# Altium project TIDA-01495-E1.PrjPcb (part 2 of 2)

## Sheet TIDA-01495-LLC.SchDoc: LLC
size 431 x 317 mm; Date: Not shown in title block; ApprovedBy: Not shown in title block; CheckedBy: Not shown in title block; Author: Not shown in title block; CompanyName: Not shown in title block; DrawnBy: Ramkumar S; Engineer: Ramkumar S; Organization: Not shown in title block; Address1: Not shown in title block; Address2: Not shown in title block; Address3: Not shown in title block; Address4: Not shown in title block; DocumentNumber: 1; Revision: Use project parameter SCH_Rev; SheetNumber: 3; SheetTotal: 4; PageSetup: Record=PageOptions¦CenterHorizontal=True¦CenterVertical=True¦PrintScale=1.00¦XCorrection=1.00¦YCorrection=1.00¦PrintKind=0¦BorderSize=5000000¦LeftOffset=0¦BottomOffset=0¦Orientation=2¦PaperLength=1000¦PaperWidth=1000¦Scale=100¦PaperSource=15¦PrintQuality=600¦MediaType=1¦DitherType=10¦PaperKind=Letter¦PrintScaleMode=1
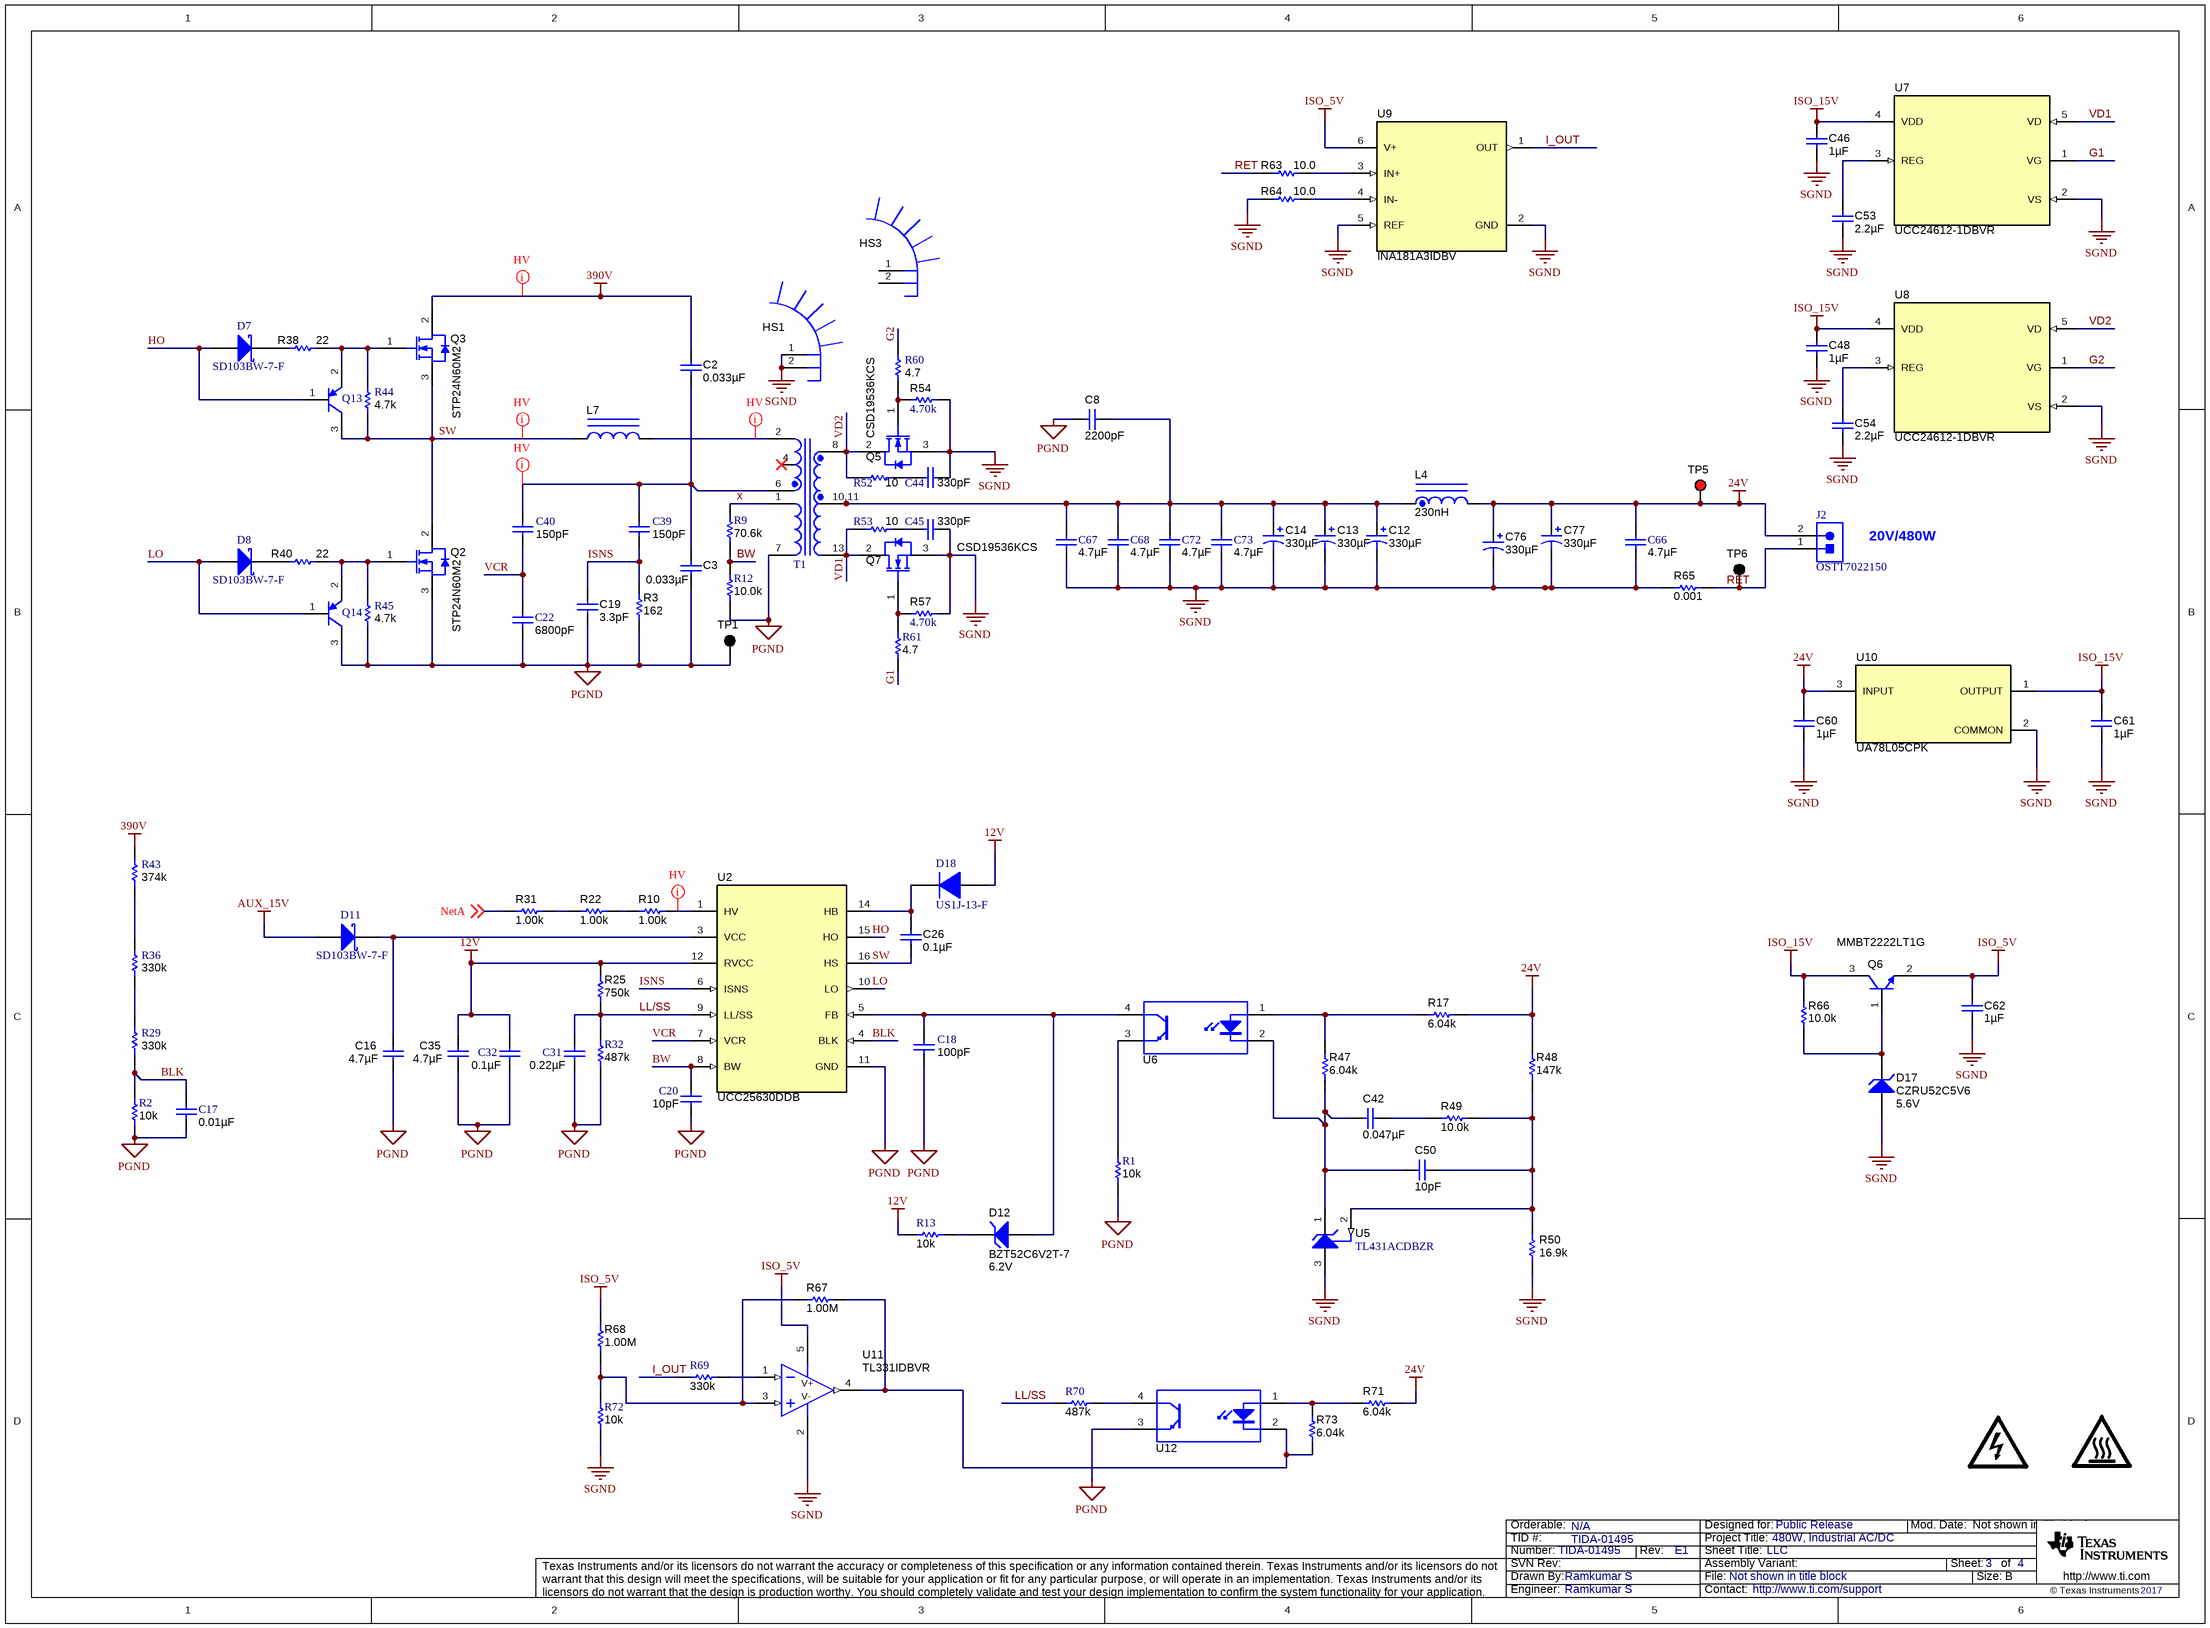
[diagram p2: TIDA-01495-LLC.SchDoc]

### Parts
(Parts that share a designator on the sheet are numbered #1, #2 ... from top to bottom, then left to right.)
C2  ValueDisplayed: 0.033µF  [B32652_1800x700x1250]  (hidden comment: B32642B0333J)
C3  ValueDisplayed: 0.033µF  [B32652_1800x700x1250]  (hidden comment: B32642B0333J)
C8  ValueDisplayed: 2200pF  [CD45_700x600x1100]  (hidden comment: AY2222M35Y5US63L7)
C12  ValueDisplayed: 330µF  [Chemi-Con_1000x2000]  (hidden comment: 35ZLH330MEFC10X12.5)
C13  ValueDisplayed: 330µF  [Chemi-Con_1000x2000]  (hidden comment: 35ZLH330MEFC10X12.5)
C14  ValueDisplayed: 330µF  [Chemi-Con_1000x2000]  (hidden comment: 35ZLH330MEFC10X12.5)
C16  ValueDisplayed: 4.7µF  [0603]  (hidden comment: 0603ZD475KAT2A)
C17  ValueDisplayed: 0.01µF  [0603]  (hidden comment: 06031C103JAT2A)
C18  ValueDisplayed: 100pF  [0603]  (hidden comment: C0603C101J5GAC)
C19  ValueDisplayed: 3.3pF  [0805_HV1]  (hidden comment: 08055A3R3CAT2A)
C20  ValueDisplayed: 10pF  [0603]  (hidden comment: 06035A100JAT2A)
C22  ValueDisplayed: 6800pF  [0603]  (hidden comment: GRM188R71H682KA01D)
C26  ValueDisplayed: 0.1µF  [0805_HV1]  (hidden comment: C0805C104K1RACTU)
C31  ValueDisplayed: 0.22µF  [0603]  (hidden comment: 06033D224KAT2A)
C32  ValueDisplayed: 0.1µF  [0603]  (hidden comment: GRM188R72A104KA35J)
C35  ValueDisplayed: 4.7µF  [0603]  (hidden comment: 0603ZD475KAT2A)
C39  ValueDisplayed: 150pF  [1206]  (hidden comment: GRM31A7U3A151JW31D)
C40  ValueDisplayed: 150pF  [1206]  (hidden comment: GRM31A7U3A151JW31D)
C42  ValueDisplayed: 0.047µF  [0603]  (hidden comment: GRM188R71C473KA01D)
C44  ValueDisplayed: 330pF  [0603]  (hidden comment: GRM1885C2A331JA01D)
C45  ValueDisplayed: 330pF  [0603]  (hidden comment: GRM1885C2A331JA01D)
C46  ValueDisplayed: 1µF  [0805_HV1]  (hidden comment: C0805C105K3RACTU)
C48  ValueDisplayed: 1µF  [0805_HV1]  (hidden comment: C0805C105K3RACTU)
C50  ValueDisplayed: 10pF  [0603]  (hidden comment: 06035A100JAT2A)
C53  ValueDisplayed: 2.2µF  [0603]  (hidden comment: C1608X6S1C225K080AC)
C54  ValueDisplayed: 2.2µF  [0603]  (hidden comment: C1608X6S1C225K080AC)
C60  ValueDisplayed: 1µF  [0603]  (hidden comment: GRM188R71E105KA12D)
C61  ValueDisplayed: 1µF  [0603]  (hidden comment: GRM188R71E105KA12D)
C62  ValueDisplayed: 1µF  [0603]  (hidden comment: GRM188R71E105KA12D)
C66  ValueDisplayed: 4.7µF  [1210]  (hidden comment: C3225X7S2A475K200AE)
C67  ValueDisplayed: 4.7µF  [1210]  (hidden comment: C3225X7S2A475K200AE)
C68  ValueDisplayed: 4.7µF  [1210]  (hidden comment: C3225X7S2A475K200AE)
C72  ValueDisplayed: 4.7µF  [1210]  (hidden comment: C3225X7S2A475K200AE)
C73  ValueDisplayed: 4.7µF  [1210]  (hidden comment: C3225X7S2A475K200AE)
C76  ValueDisplayed: 330µF  [Chemi-Con_1000x2000]  (hidden comment: 35ZLH330MEFC10X12.5)
C77  ValueDisplayed: 330µF  [Chemi-Con_1000x2000]  (hidden comment: 35ZLH330MEFC10X12.5)
D7  SD103BW-7-F  [SOD-123]
D8  SD103BW-7-F  [SOD-123]
D11  SD103BW-7-F  [SOD-123]
D12  BZT52C6V2T-7  value 6.2V  [SOD-523]
D17  CZRU52C5V6  value 5.6V  [SOD-523F]
D18  US1J-13-F  [SMA]
HS1  782653B04250G  [HEATSINK_782653B04250G]  (value not drawn)
HS3  782653B04250G  [HEATSINK_782653B04250G]  (value not drawn)
J2  OSTT7022150  [TERM_BLK_OSTT7022150]
L4  ValueDisplayed: 230nH  [THCBR1290]  (hidden comment: THCBR1290-231IN)
L7  (no value)  [IND_CUST]
LOGO?#5  DANGER HIGH VOLTAGE  [IEC_HighVoltage_Small]  (value not drawn)  (graphical)
LOGO?#6  CAUTION HOT SURFACE  [IEC_HotSurface_Small]  (value not drawn)  (graphical)
Q2  STP24N60M2  [TO-220AB_HORIZONTAL]
Q3  STP24N60M2  [TO-220AB_HORIZONTAL]
Q5  CSD19536KCS  [TO-220AB_HORIZONTAL]
Q6  MMBT2222LT1G  [SOT-23]
Q7  CSD19536KCS  [TO-220AB_HORIZONTAL]
Q13  BC858C-7-F  [SOT-23]  (value not drawn)
Q14  BC858C-7-F  [SOT-23]  (value not drawn)
R1  ValueDisplayed: 10k  [0603]  (hidden comment: RNCF0603TKY10K0)
R2  ValueDisplayed: 10k  [0603]  (hidden comment: RNCF0603TKY10K0)
R3  ValueDisplayed: 162  [0805_HV1]  (hidden comment: CRCW0805162RFKEA)
R9  ValueDisplayed: 70.6k  [0603]  (hidden comment: RT0603DRE0770K6L)
R10  ValueDisplayed: 1.00k  [1206]  (hidden comment: CRCW12061K00FKEA)
R12  ValueDisplayed: 10.0k  [0603]  (hidden comment: CRCW060310K0FKEA)
R13  ValueDisplayed: 10k  [0603]  (hidden comment: RNCF0603TKY10K0)
R17  ValueDisplayed: 6.04k  [0603]  (hidden comment: CRCW06036K04FKEA)
R22  ValueDisplayed: 1.00k  [1206]  (hidden comment: CRCW12061K00FKEA)
R25  ValueDisplayed: 750k  [0603]  (hidden comment: CRCW0603750KFKEA)
R29  ValueDisplayed: 330k  [1206]  (hidden comment: CRCW1206330KJNEA)
R31  ValueDisplayed: 1.00k  [1206]  (hidden comment: CRCW12061K00FKEA)
R32  ValueDisplayed: 487k  [0603]  (hidden comment: CRCW0603487KFKEA)
R36  ValueDisplayed: 330k  [1206]  (hidden comment: CRCW1206330KJNEA)
R38  ValueDisplayed: 22  [0603]  (hidden comment: CRCW060322R0JNEA)
R40  ValueDisplayed: 22  [0603]  (hidden comment: CRCW060322R0JNEA)
R43  ValueDisplayed: 374k  [1206]  (hidden comment: CRCW1206374KFKEA)
R44  ValueDisplayed: 4.7k  [0603]  (hidden comment: CR0603-JW-472GLF)
R45  ValueDisplayed: 4.7k  [0603]  (hidden comment: CR0603-JW-472GLF)
R47  ValueDisplayed: 6.04k  [0603]  (hidden comment: CRCW06036K04FKEA)
R48  ValueDisplayed: 147k  [0603]  (hidden comment: CRCW0603147KFKEA)
R49  ValueDisplayed: 10.0k  [0603]  (hidden comment: CRCW060310K0FKEA)
R50  ValueDisplayed: 16.9k  [0603]  (hidden comment: CRCW060316K9FKEA)
R52  ValueDisplayed: 10  [0805_HV1]  (hidden comment: CRCW080510R0JNEA)
R53  ValueDisplayed: 10  [0805_HV1]  (hidden comment: CRCW080510R0JNEA)
R54  ValueDisplayed: 4.70k  [1206]  (hidden comment: RC1206FR-074K7L)
R57  ValueDisplayed: 4.70k  [1206]  (hidden comment: RC1206FR-074K7L)
R60  ValueDisplayed: 4.7  [0805_HV1]  (hidden comment: CRCW08054R70JNEA)
R61  ValueDisplayed: 4.7  [0805_HV1]  (hidden comment: CRCW08054R70JNEA)
R63  ValueDisplayed: 10.0  [0603]  (hidden comment: RC0603FR-0710RL)
R64  ValueDisplayed: 10.0  [0603]  (hidden comment: RC0603FR-0710RL)
R65  ValueDisplayed: 0.001  [2512]  (hidden comment: ERJ-M1WTF1M0U)
R66  ValueDisplayed: 10.0k  [0603]  (hidden comment: CRCW060310K0FKEA)
R67  ValueDisplayed: 1.00M  [0603]  (hidden comment: MCT06030C1004FP500)
R68  ValueDisplayed: 1.00M  [0603]  (hidden comment: MCT06030C1004FP500)
R69  ValueDisplayed: 330k  [1206]  (hidden comment: CRCW1206330KJNEA)
R70  ValueDisplayed: 487k  [0603]  (hidden comment: CRCW0603487KFKEA)
R71  ValueDisplayed: 6.04k  [0603]  (hidden comment: CRCW06036K04FKEA)
R72  ValueDisplayed: 10k  [0603]  (hidden comment: RNCF0603TKY10K0)
R73  ValueDisplayed: 6.04k  [0603]  (hidden comment: CRCW06036K04FKEA)
T1  58599  [WE_750343661_CUS]  (value not drawn)
TP1  5001  [Keystone5001]  (value not drawn)
TP5  5000  [Keystone5000]  (value not drawn)
TP6  5001  [Keystone5001]  (value not drawn)
U2  UCC25630DDB  [DDB0014A]
U5  TL431ACDBZR  [DBZ0003A_N]
U6  VO618A  [DIP-4]  (value not drawn)
U7  UCC24612-1DBVR  [DBV0005A_N]
U8  UCC24612-1DBVR  [DBV0005A_N]
U9  INA181A3IDBV  [DBV0006A_N]
U10  UA78L05CPK  [PK0003A_M]
U11  TL331IDBVR  [DBV0005A_N]
U12  VO618A  [DIP-4]  (value not drawn)

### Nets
12V: C32.1 C35.1 D18.2(A) R13.1 R25.2 U2.12(RVCC)
24V: C60.1 C66.1 C76.1(+) C77.1(+) J2.2 L4.2 R17.2 R48.2 R71.2 TP5.1 U10.3(INPUT)
390V: C2.1 Q3.2(D) R43.2
AUX_15V: D11.2(A)
ISO_5V: C62.1 Q6.2(E) R68.2 U9.6(V+) U11.5(V+)
ISO_15V: C46.1 C48.1 C61.1 Q6.3(C) R66.1 U7.4(VDD) U8.4(VDD) U10.1(OUTPUT)
PGND: C3.2 C8.2 C16.2 C17.1 C18.2 C19.2 C20.2 C22.2 C31.2 C32.2 C35.2 Q2.3(S) Q14.3(C) R1.1 R2.1 R3.1 R12.1 R32.1 R45.1 T1.7 TP1.1 U2.11(GND) U12.3(E)
SGND: C12.2(-) C13.2(-) C14.2(-) C44.1 C45.1 C46.2 C48.2 C53.2 C54.2 C60.2 C61.2 C62.2 C66.2 C67.2 C68.2 C72.2 C73.2 C76.2(-) C77.2(-) D17.2(A) HS1.1 HS1.2 Q5.3(S) Q7.3(S) R50.1 R54.2 R57.2 R64.1 R65.1 R72.1 U5.3(ANODE) U7.2(VS) U8.2(VS) U9.2(GND) U9.5(REF) U10.2(COMMON) U11.2(V-/GND)
BLK: C17.2 R2.2 R29.1 U2.4(BLK)
BW: C20.1 R9.1 R12.2 U2.8(BW)
G1: R61.1 U7.1(VG)
G2: R60.2 U8.1(VG)
HO: D7.2(A) Q13.1(B) U2.15(HO)
I_OUT: R69.2 U9.1(OUT)
ISNS: C19.1 C39.2 R3.2 U2.6(ISNS)
LL/SS: C31.1 R25.1 R32.2 R70.2 U2.9(LL/SS)
LO: D8.2(A) Q14.1(B) U2.10(LO)
NetA: R31.1 ; off-sheet NetA
RET: J2.1 R63.1 R65.2 TP6.1
SW: C26.2 L7.1 Q2.2(D) Q3.3(S) Q13.3(C) R44.1 U2.16(HS)
VCR: C22.1 C40.2 U2.7(VCR)
VD1: Q7.2(D) R53.1 T1.13 U7.5(VD)
VD2: Q5.2(D) R52.1 T1.8 U8.5(VD)
x: R9.2 T1.1
NetC2_2: C2.2 C3.1 C39.1 C40.1 T1.6
NetC8_1: C8.1 C12.1(+) C13.1(+) C14.1(+) C67.1 C68.1 C72.1 C73.1 L4.1 T1.10,11 T1.11
NetC16_1: C16.1 D11.1(K) U2.3(VCC)
NetC18_1: C18.1 D12.2(A) U2.5(FB) U6.4(C)
NetC26_1: C26.1 D18.1(K) U2.14(HB)
NetC42_1: C42.1 R49.1
NetC42_2: C42.2 C50.2 R47.1 U5.1(CATHODE) U6.2(K)
NetC44_2: C44.2 R52.2
NetC45_2: C45.2 R53.2
NetC50_1: C50.1 R48.1 R49.2 R50.2 U5.2(REF)
NetC53_1: C53.1 U7.3(REG)
NetC54_1: C54.1 U8.3(REG)
NetD7_1: D7.1(K) R38.1
NetD8_1: D8.1(K) R40.1
NetD12_1: D12.1(K) R13.2
NetD17_1: D17.1(K) Q6.1(B) R66.2
NetL7_2: L7.2 T1.2
NetQ2_1: Q2.1(G) Q14.2(E) R40.2 R45.2
NetQ3_1: Q3.1(G) Q13.2(E) R38.2 R44.2
NetQ5_1: Q5.1(G) R54.1 R60.1
NetQ7_1: Q7.1(G) R57.1 R61.2
NetR1_2: R1.2 U6.3(E)
NetR10_1: R10.1 R22.2
NetR10_2: R10.2 U2.1(HV)
NetR17_1: R17.1 R47.2 U6.1(A)
NetR22_1: R22.1 R31.2
NetR29_2: R29.2 R36.1
NetR36_2: R36.2 R43.1
NetR63_2: R63.2 U9.3(IN+)
NetR64_2: R64.2 U9.4(IN-)
NetR67_1: R67.1 R68.1 R72.2 U11.3(IN+)
NetR67_2: R67.2 R73.1 U11.4(OUT) U12.2(K)
NetR69_1: R69.1 U11.1(IN-)
NetR70_1: R70.1 U12.4(C)
NetR71_1: R71.1 R73.2 U12.1(A)

Not connected (* = marked no-connect by the designer): HS3 1 2; T1 4*

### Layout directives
net class HV: 390V, NetC2_2, NetL7_2, NetR10_2, SW

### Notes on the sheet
- 20V/480W

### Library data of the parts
C2 C3 = B32652A7153J000: CAP FILM 0.033UF 5% 1KVDC RADIAL; Manufacturer: TDK; Polarized: N; CompType: Capacitor; U/M: EA; Cap_F: 0.000000033; Tolerance_%: 5; VDC_V: 1250; Value2: 1250V; TaMin_C: -55; TaMax_C: 100; Cap_Case: 18x7x12.5; SizeAreaWB_mm2: 180; SizeArea_mm2: 126; SizeX_mm: 18; SizeY_mm: 7; SizeZ_mm: 12.5; AEC Category: Q200; AEC Qualified: Y; AEC Grade: 3; Green_Lifecycle: Not Set; Green_REACh: Incomplete; VAC: 500
C8 = AY2222M35Y5US63L7: CAP, CERM, 2200 pF, 300 V, +/- 20%, Y5U, AEC-Q200 Grade 1, D9.5xT5mm; Manufacturer: Vishay-Bccomponents; Polarized: N; CompType: Capacitor; Value: 2200pF; U/M: EA; Cap_F: 0.0000000022; Tolerance_%: 20; Value1: Unknown; VDC_V: 300; Value2: 300V; TaMin_C: -55; TaMax_C: 125; Cap_Case: 9.5x5mm; SizeArea_mm2: 47.5; SizeAreaWB_mm2: 80.5; SizeX_mm: 9.5; SizeY_mm: 5; SizeZ_mm: 14.5; AEC Category: Q200; AEC Qualified: Y; AEC Grade: 1
C12-C14 C76 C77 = EKZE350ELL471MJ20S: CAP, AL, 330 µF, 35 V, +/- 20%, TH; Manufacturer: Rubycon; Polarized: Y; CompType: Capacitor; Value: 330uF; U/M: EA; Cap_F: 0.00047; Tolerance_%: 20; VDC_V: 35; Value2: 35V; IRMS_A: 1.82; TaMin_C: -40; TaMax_C: 105; Cap_Case: 10x20; SizeAreaWB_mm2: 144; SizeArea_mm2: 100; SizeX_mm: 10; SizeZ_mm: 21.5; AEC Category: Q200; AEC Qualified: N
C16 C35 = 0603ZD475KAT2A: CAP, CERM, 4.7 µF, 10 V, +/- 10%, X5R, 0603; Manufacturer: AVX; Polarized: N; CompType: Capacitor; Value: 4.7uF; U/M: EA; Cap_F: 0.0000047; Tolerance_%: 10; Value1: Unknown; Value2: 10V; TaMin_C: -55; TaMax_C: 85; SizeArea_mm2: 1.28; SizeAreaWB_mm2: 4.68; SizeX_mm: 1.6; SizeY_mm: 0.8; SizeZ_mm: 1; AEC Category: Q200; Green_Lifecycle: Active; Green_REACh: Passed
C17 = 06031C103JAT2A: CAP, CERM, 0.01 µF, 100 V, +/- 5%, X7R, 0603; Manufacturer: AVX; Polarized: N; CompType: Capacitor; Value: 0.01uF; U/M: EA; Cap_F: 0.00000001; Tolerance_%: 5; ESR_ohm: 0.098; Value1: 0.098 ohm; VDC_V: 100; Value2: 100V; TaMin_C: -55; TaMax_C: 125
C18 = C0603C101J5GAC: CAP, CERM, 100 pF, 50 V, +/- 5%, C0G/NP0, 0603; Manufacturer: Kemet; Polarized: N; CompType: Capacitor; Value: 100pF; U/M: EA; Cap_F: 0.0000000001; Tolerance_%: 5; Value1: Unknown; VDC_V: 50; Value2: 50V; TaMin_C: -55; TaMax_C: 125
C19 = 08055A3R3CAT2A: CAP, CERM, 3.3 pF, 50 V, +/- 8%, C0G/NP0, 0805; Manufacturer: AVX; Polarized: N; CompType: Capacitor; Value: 3.3pF; U/M: EA; Cap_F: 0.0000000000033; Tolerance_%: 8; ESR_ohm: 3.467; Value1: 3.467 ohm; VDC_V: 50; Value2: 50V; TaMin_C: -55; TaMax_C: 125; Cap_Case: 0805; SizeArea_mm2: 2.5; SizeAreaWB_mm2: 6.75; SizeX_mm: 2; SizeY_mm: 1.25; SizeZ_mm: 1.45; AEC Category: Q200; Green_Lifecycle: Not Set; Green_REACh: Incomplete
C20 = 06035A100JAT2A: CAP, CERM, 10 pF, 50 V, +/- 5%, C0G/NP0, 0603; Manufacturer: AVX; Polarized: N; CompType: Capacitor; Value: 10pF; U/M: EA; Cap_F: 0.00000000001; Tolerance_%: 5; ESR_ohm: 0.403; Value1: 0.403 ohm; VDC_V: 50; Value2: 50V; TaMin_C: -55; TaMax_C: 125
C22 = GRM188R71H682KA01D: CAP, CERM, 6800 pF, 50 V, +/- 10%, X7R, 0603; Manufacturer: MuRata; Polarized: N; CompType: Capacitor; Value: 6800pF; U/M: EA; Cap_F: 0.0000000068; Tolerance_%: 10; Value1: Unknown; VDC_V: 50; Value2: 50V; TaMin_C: -55; TaMax_C: 125
C26 = C0805C104K1RACTU: CAP, CERM, 0.1 µF, 100 V,+/- 10%, X7R, 0805; Manufacturer: Kemet; Polarized: N; CompType: Capacitor; Value: 0.1uF; U/M: EA; Cap_F: 0.0000001; Tolerance_%: 10; ESR_ohm: 0.064; Value1: 0.064 ohm; VDC_V: 100; Value2: 100V; IRMS_A: 1.64; TaMin_C: -55; TaMax_C: 125; Cap_Case: 0805; SizeArea_mm2: 2.5; SizeAreaWB_mm2: 6.75; SizeX_mm: 2; SizeY_mm: 1.25; SizeZ_mm: 1.45; AEC Category: Q200; Green_Lifecycle: Active; Green_REACh: Passed
C31 = 06033D224KAT2A: CAP, CERM, 0.22 µF, 25 V, +/- 10%, X5R, 0603; Manufacturer: AVX; Polarized: N; CompType: Capacitor; Value: 0.22uF; U/M: EA; Cap_F: 0.00000022; Tolerance_%: 10; ESR_ohm: 0.036; Value1: 0.036 ohm; VDC_V: 25; Value2: 25V; TaMin_C: -55; TaMax_C: 85
C32 = GRM188R72A104KA35J: CAP, CERM, 0.1 µF, 100 V, +/- 10%, X7R, 0603; Manufacturer: MuRata; Polarized: N; CompType: Capacitor; Value: 0.1uF; U/M: EA; Cap_F: 0.0000001; Tolerance_%: 10; Value1: Unknown; VDC_V: 100; Value2: 100V; TaMin_C: -55; TaMax_C: 125
C39 C40 = GRM31A7U3A151JW31D: CAP, CERM, 150 pF, 1000 V, +/- 5%, U2J, 1206; Manufacturer: MuRata; Polarized: N; CompType: Capacitor; Value: 150pF; U/M: EA; Cap_F: 0.00000000015; Tolerance_%: 5; Value1: Unknown; VDC_V: 1000; Value2: 1000V; TaMin_C: -55; TaMax_C: 125
C42 = GRM188R71C473KA01D: CAP, CERM, 0.047 µF, 16 V,+/- 10%, X7R, 0603; Manufacturer: MuRata; Polarized: N; CompType: Capacitor; Value: 0.047uF; U/M: EA; Cap_F: 0.000000047; Tolerance_%: 10; VDC_V: 16; Value2: 16V; TaMin_C: -55; TaMax_C: 125; SizeArea_mm2: 1.28; SizeAreaWB_mm2: 4.68; SizeX_mm: 1.6; SizeY_mm: 0.8; SizeZ_mm: 1; AEC Category: Q200; Green_Lifecycle: Active; Green_REACh: Passed
C44 C45 = GRM1885C2A331JA01D: CAP, CERM, 330 pF, 100 V, +/- 5%, C0G/NP0, 0603; Manufacturer: MuRata; Polarized: N; CompType: Capacitor; Value: 330pF; U/M: EA; Cap_F: 0.00000000033; Tolerance_%: 5; Value1: Unknown; VDC_V: 100; Value2: 100V; TaMin_C: -55; TaMax_C: 125
C46 C48 = C0805C105K3RACTU: CAP, CERM, 1 µF, 25 V, +/- 10%, X7R, 0805; Manufacturer: Kemet; Polarized: N; CompType: Capacitor; Value: 1uF; U/M: EA; Cap_F: 0.000001; Tolerance_%: 10; Value1: Unknown; VDC_V: 25; Value2: 25V; TaMin_C: -55; TaMax_C: 125; Cap_Case: 0805; SizeArea_mm2: 2.5; SizeAreaWB_mm2: 6.75; SizeX_mm: 2; SizeY_mm: 1.25; SizeZ_mm: 1.45; AEC Category: Q200; Green_Lifecycle: Active; Green_REACh: Passed
C50 = 06035A100JAT2A: CAP, CERM, 10 pF, 50 V,+/- 5%, C0G/NP0, 0603; Manufacturer: AVX; Polarized: N; CompType: Capacitor; Value: 10pF; U/M: EA; Cap_F: 0.00000000001; Tolerance_%: 5; ESR_ohm: 0.403; Value1: 0.403 ohm; VDC_V: 50; Value2: 50V; TaMin_C: -55; TaMax_C: 125; SizeArea_mm2: 1.28; SizeAreaWB_mm2: 4.68; SizeX_mm: 1.6; SizeY_mm: 0.8; SizeZ_mm: 1; AEC Category: Q200; Green_Lifecycle: Active; Green_REACh: Passed
C53 C54 = C1608X6S1C225K080AC: CAP, CERM, 2.2 µF, 16 V, +/- 10%, X6S, 0603; Manufacturer: TDK; Polarized: N; CompType: Capacitor; Value: 2.2uF; U/M: EA; Cap_F: 0.0000022; Tolerance_%: 10; ESR_ohm: 0.007674; Value1: 0.007674 ohm; VDC_V: 16; Value2: 16V; IRMS_A: 1.87823; TaMin_C: -55; TaMax_C: 105; SizeArea_mm2: 1.28; SizeAreaWB_mm2: 4.68; SizeX_mm: 1.6; SizeY_mm: 0.8; SizeZ_mm: 1; AEC Category: Q200
C60-C62 = GRM188R71E105KA12D: CAP, CERM, 1 µF, 25 V, +/- 10%, X7R, 0603; Manufacturer: MuRata; Polarized: N; CompType: Capacitor; Value: 1uF; U/M: EA; Cap_F: 0.000001; Tolerance_%: 10; Value1: Unknown; VDC_V: 25; Value2: 25V; TaMin_C: -55; TaMax_C: 125
C66-C68 C72 C73 = C3225X7S2A475K200AE: CAP, CERM, 4.7 µF, 100 V, +/- 10%, X7S, 1210; Manufacturer: TDK; Polarized: N; CompType: Capacitor; Value: 4.7uF; U/M: EA; Cap_F: 0.0000047; Tolerance_%: 10; Value1: Unknown; VDC_V: 100; Value2: 100V; TaMin_C: -55; TaMax_C: 125
D7 D8 D11 = SD103BW-7-F: Diode, Schottky, 30 V, 0.35 A, SOD-123; Manufacturer: Diodes Inc.; U/M: EA; Vf_V: 0.55; Value: 30V; Value1: 0.35A; Value2: 0.55V; Io_A: 0.35; Vr_V: 30
D12 = BZT52C6V2T-7: Diode, Zener, 6.2 V, 300 mW, SOD-523; Manufacturer: Diodes Inc.; SymbolCreator: a0412235; U/M: EA; Power_W: 0.3; Vz_V: 6.2; Value1: 0.3W; RJA_CperW: 417; SizeAreaWB_mm2: 5.13; SizeArea_mm2: 1.53; SizeX_mm: 1.7; SizeY_mm: 0.9; SizeZ_mm: 0.65; AEC Category: Q101
D17 = CMP-0005912-1: Diode, Zener, 5.6 V, 150 mW, SOD-523F; Manufacturer: Comchip Technology; Power_W: 150mW; SizeAreaWB_mm2: 5.13; Value1: 0.15W; U/M: EA; SizeZ_mm: 0.85; SizeX_mm: 1.7; SizeY_mm: 0.9; SizeArea_mm2: 1.53; AEC Category: Q101
D18 = US1J-13-F: Diode, Ultrafast, 600 V, 1 A, SMA; Manufacturer: Diodes Inc.; U/M: EA; Vf_V: 1.7; Value: 600V; Value1: 1A; Value2: 1.7V; Io_A: 1; Vr_V: 600; TJmax_C: 150
HS1 HS3 = 782653B04250G: HEATSINK VERT MAX CLIP, BLACK, 4.25 INCHES; Manufacturer: Aavid; SymbolCreator: a0411947
J2 = OSTT7022150: Terminal Block, 30A, 9.52mm (.375) Pitch, 2-Pos, TH; Manufacturer: On-Shore Technology; SymbolCreator: a0412235; CompType: Connector; U/M: EA
L4 = THCBR1290-231IN: Inductor, Ferrite, 230 nH, 56 A, 0.0005 ohm, TH; Manufacturer: Delta Electronics Inc.; Value: 230nH; SymbolCreator: a0412235; Ind_H: 230.0E-9; Imax_A: 56; Irms: 0A @ 0C rise; Isat: 56A @ 0% inductance drop; DCR_ohm: 0.0005; Value2: 56A; SizeAreaWB_mm2: 151.8; SizeArea_mm2: 106.2; SizeX_mm: 11.8; SizeY_mm: 9; SizeZ_mm: 9.2; AEC Category: Q200; Green_Lifecycle: Not Set; Green_REACh: Incomplete
L7 = 1140-331K-RC: Inductor, Ferrite, 330 µH, 6.1 A, 0.074 ohm, TH; DCR_ohm: 0.074; AEC Category: Q200
LOGO?#5 = IEC_HighVoltage: IEC 61010-1 High Voltage Warning; SymbolCreator: a0412235
LOGO?#6 = IEC_HotSurface: IEC 61010-1 Hot Surface Warning; SymbolCreator: a0412235
Q2 Q3 = IPP60R190P6: MOSFET, N-CH, 650 V, 20.2 A, TO-220AB; Manufacturer: STMicroelectronics; Alternate Manufacturer: None; U/M: EA; ChType: N; Value: 650V; VdsMax_V: 650; Value1: ? ohm; Value2: 37 nC; QgTyp_nC: 37; Vgs_V: 20; IdsMax_A: 20.2; SizeAreaWB_mm2: 79.3; SizeArea_mm2: 45.9; SizeX_mm: 10.2; SizeY_mm: 4.5; SizeZ_mm: 19.4; AEC Category: Q101
Q5 Q7 = CSD19536KCS: MOSFET, N-CH, 100 V, 150 A, KCS0003B (TO-220-3); Manufacturer: Texas Instruments; Alternate Manufacturer: None; U/M: EA; ChType: N; Value: 100V; VdsMax_V: 100; Value1: ? ohm; Value2: 118 nC; QgTyp_nC: 118; Vgs_V: 20; IdsMax_A: 150; SizeAreaWB_mm2: 79.648; SizeArea_mm2: 46.228; SizeX_mm: 4.55; SizeY_mm: 10.16; SizeZ_mm: 20.45; AEC Category: Q101
Q6 = CMP-0000421-2: Transistor, NPN, 30 V, 0.6 A, SOT-23; Manufacturer: ON Semiconductor; TaMax_C: 150°C; Value2: 300; Value1: 0.6 A; Vcesat1_V: 1.6V; SizeX_mm: 2.5; SizeY_mm: 3; TaMin_C: -55°C; IcRated_A: 6dA; CompType: BJT; SizeZ_mm: 1.1; Value: 30 V; SizeArea_mm2: 7.5; NPN: 1; Vceo_V: 30V; PNP: 0; AEC Category: Q101; SizeAreaWB_mm2: 14; U/M: EA
Q13 Q14 = BC858C-7-F, Diodes Inc.: Transistor, PNP, 30 V, 0.1 A, SOT-23; CompType: BJT; PNP: 1; NPN: 0; Vceo_V: 30; Vcesat1_V: 0.075; Value: 30 V; IcRated_A: 0.1; Value1: 0.1 A; HfeMax: 600; TaMin_C: -65; TaMax_C: 150; U/M: EA
R1 R2 R13 R72 = RNCF0603TKY10K0: RES, 10 k, 0.01%, 0.063 W, 0603; Manufacturer: Stackpole Electronics Inc; CompType: Resistor; Value: 10k; Res_ohm: 10000; Value_Code: 10k0; Tolerance_%: 0.01; Power_W: 0.063; Value2: 0.063W; VDC_V: 50; TempCo: 5 ppm/C; U/M: EA
R3 = CRCW0805162RFKEA: RES, 162, 1%, 0.125 W, 0805; Manufacturer: Vishay-Dale; CompType: Resistor; Value: 162; Value_Code: 162R; Tolerance_%: 1; Power_W: 0.125; Value2: 0.125W; VDC_V: 150; TempCo: 100 ppm/C; SizeArea_mm2: 2.5; SizeX_mm: 2; SizeY_mm: 1.25; SizeZ_mm: 1.45; EIA_Code: E96; U/M: EA; AEC Category: Q200
R9 = RT0603DRE0770K6L: RES, 70.6 k, 0.5%, 0.1 W, 0603; Manufacturer: Yageo America; CompType: Resistor; Value: 70.6k; Res_ohm: 70600; Value_Code: 70k6; Tolerance_%: 0.5; Power_W: 0.1; Value2: 0.1W; VDC_V: 75; TempCo: 50 ppm/C; EIA_Code: E192; U/M: EA
R10 R22 R31 = CRCW12061K00FKEA: RES, 1.00 k, 1%, 0.25 W, 1206; Manufacturer: Vishay-Dale; CompType: Resistor; Value: 1.00k; Res_ohm: 1000; Value_Code: 1k00; Tolerance_%: 1; Power_W: 0.25; Value2: 0.25W; VDC_V: 200; TempCo: 100 ppm/C; SizeArea_mm2: 5.12; SizeX_mm: 3.2; SizeY_mm: 1.6; SizeZ_mm: 1.35; EIA_Code: E96; U/M: EA; AEC Category: Q200; Green_Lifecycle: Active; Green_REACh: Passed
R12 = CRCW060310K0FKEA: RES, 10.0 k, 1%, 0.1 W, 0603; Manufacturer: Vishay-Dale; CompType: Resistor; Value: 10.0k; Res_ohm: 10000; Value_Code: 10k0; Tolerance_%: 1; Power_W: 0.1; Value2: 0.1W; VDC_V: 75; TempCo: 100 ppm/C; EIA_Code: E96; U/M: EA
R17 R47 R71 R73 = CRCW06036K04FKEA: RES, 6.04 k, 1%, 0.1 W, 0603; Manufacturer: Vishay-Dale; CompType: Resistor; Value: 6.04k; Res_ohm: 6040; Value_Code: 6k04; Tolerance_%: 1; Power_W: 0.1; Value2: 0.1W; VDC_V: 75; TempCo: 100 ppm/C; SizeArea_mm2: 1.28; SizeX_mm: 1.6; SizeY_mm: 0.8; EIA_Code: E96; U/M: EA; AEC Category: Q200; Green_Lifecycle: Active; Green_REACh: Passed
R25 = CRCW0603750KFKEA: RES, 750 k, 1%, 0.1 W, 0603; Manufacturer: Vishay-Dale; CompType: Resistor; Value: 750k; Res_ohm: 750000; Tolerance_%: 1; Power_W: 0.1; Value2: 0.1W; VDC_V: 75; TempCo: 100 ppm/C; SizeArea_mm2: 1.28; SizeX_mm: 1.6; SizeY_mm: 0.8; EIA_Code: E96; U/M: EA; AEC Category: Q200; Green_Lifecycle: Active; Green_REACh: Passed
R29 R36 R69 = CRCW1206330KJNEA: RES, 330 k, 5%, 0.25 W, 1206; Manufacturer: Vishay-Dale; CompType: Resistor; Value: 330k; Res_ohm: 330000; Tolerance_%: 5; Power_W: 0.25; Value2: 0.25W; VDC_V: 200; TempCo: 200 ppm/C; EIA_Code: E24; U/M: EA
R32 R70 = CRCW0603487KFKEA: RES, 487 k, 1%, 0.1 W, 0603; Manufacturer: Vishay-Dale; CompType: Resistor; Value: 487k; Res_ohm: 487000; Tolerance_%: 1; Power_W: 0.1; Value2: 0.1W; VDC_V: 75; TempCo: 100 ppm/C; EIA_Code: E96; U/M: EA
R38 R40 = CRCW060322R0JNEA: RES, 22, 5%, 0.1 W, 0603; Manufacturer: Vishay-Dale; CompType: Resistor; Value: 22; Value_Code: 22R0; Tolerance_%: 5; Power_W: 0.1; Value2: 0.1W; VDC_V: 75; TempCo: 200 ppm/C; SizeArea_mm2: 1.28; SizeX_mm: 1.6; SizeY_mm: 0.8; SizeZ_mm: 1; EIA_Code: E24; U/M: EA; AEC Category: Q200
R43 = CRCW1206374KFKEA: RES, 374 k, 1%, 0.25 W, 1206; Manufacturer: Vishay-Dale; CompType: Resistor; Value: 374k; Res_ohm: 374000; Tolerance_%: 1; Power_W: 0.25; Value2: 0.25W; VDC_V: 200; TempCo: 100 ppm/C; EIA_Code: E96; U/M: EA
R44 R45 = CR0603-JW-472GLF: RES, 4.7 k, 5%, 0.1 W, 0603; Manufacturer: Bourns; CompType: Resistor; Value: 4.7k; Res_ohm: 4700; Value_Code: 4k70; Tolerance_%: 5; Power_W: 0.1; Value2: 0.1W; VDC_V: 50; TempCo: 200 ppm/C; EIA_Code: E24; U/M: EA
R48 = CRCW0603147KFKEA: RES, 147 k, 1%, 0.1 W, 0603; Manufacturer: Vishay-Dale; CompType: Resistor; Value: 147k; Res_ohm: 147000; Tolerance_%: 1; Power_W: 0.1; Value2: 0.1W; VDC_V: 75; TempCo: 100 ppm/C; SizeArea_mm2: 1.28; SizeX_mm: 1.6; SizeY_mm: 0.8; EIA_Code: E96; U/M: EA; AEC Category: Q200; Green_Lifecycle: Active; Green_REACh: Passed
R49 R66 = CRCW060310K0FKEA: RES, 10.0 k, 1%, 0.1 W, 0603; Manufacturer: Vishay-Dale; CompType: Resistor; Value: 10.0k; Res_ohm: 10000; Value_Code: 10k0; Tolerance_%: 1; Power_W: 0.1; Value2: 0.1W; VDC_V: 75; TempCo: 100 ppm/C; SizeArea_mm2: 1.28; SizeX_mm: 1.6; SizeY_mm: 0.8; EIA_Code: E96; U/M: EA; AEC Category: Q200; Green_Lifecycle: Active; Green_REACh: Passed
R50 = CRCW060316K9FKEA: RES, 16.9 k, 1%, 0.1 W, 0603; Manufacturer: Vishay-Dale; CompType: Resistor; Value: 16.9k; Res_ohm: 16900; Value_Code: 16k9; Tolerance_%: 1; Power_W: 0.1; Value2: 0.1W; VDC_V: 75; TempCo: 100 ppm/C; SizeArea_mm2: 1.28; SizeX_mm: 1.6; SizeY_mm: 0.8; EIA_Code: E96; U/M: EA; AEC Category: Q200; Green_Lifecycle: Active; Green_REACh: Passed
R52 R53 = CRCW080510R0JNEA: RES, 10, 5%, 0.125 W, 0805; Manufacturer: Vishay-Dale; CompType: Resistor; Value: 10; Value_Code: 10R0; Tolerance_%: 5; Power_W: 0.125; Value2: 0.125W; VDC_V: 150; TempCo: 200 ppm/C; EIA_Code: E24; U/M: EA
R54 R57 = CMP-0018338-2: RES, 4.70 k, 1%, 0.25 W, 1206; Manufacturer: Yageo America; Power_W: 250mW; TempCo: 100 ppm/C; Value_Code: 4k70; U/M: EA; Value: 4.70k; Res_ohm: 4.7k; SizeX_mm: 3.2; SizeY_mm: 1.6; SizeZ_mm: 1.35; Value2: 0.25W; SizeArea_mm2: 5.12; VDC_V: 200V; AEC Category: Q200
R60 R61 = CRCW08054R70JNEA: RES, 4.7, 5%, 0.125 W, 0805; Manufacturer: Vishay-Dale; CompType: Resistor; Value: 4.7; Value_Code: 4R70; Tolerance_%: 5; Power_W: 0.125; Value2: 0.125W; VDC_V: 150; TempCo: 200 ppm/C; EIA_Code: E24; U/M: EA
R63 = CMP-0022751-4: RES, 10.0, 1%, 0.1 W, 0603; Manufacturer: Yageo; Power_W: 100mW; TempCo: 100 ppm/C; Value_Code: 10R0; Value: 10.0; EIA_Code: E96; Res_ohm: 10; SizeX_mm: 1.6; SizeY_mm: 0.8; SizeZ_mm: 1; Value2: 0.1W; SizeArea_mm2: 1.28; CompType: Resistor; AEC Qualified: N; VDC_V: 75V; AEC Category: Q200; SizeAreaWB_mm2: 4.68
R64 = CMP-0022751-4: RES, 10.0, 1%, 0.1 W, 0603; Manufacturer: Yageo; Power_W: 100mW; TempCo: 100 ppm/C; Value_Code: 10R0; Value: 10.0; EIA_Code: E96; Res_ohm: 10; SizeX_mm: 1.6; SizeY_mm: 0.8; SizeZ_mm: 1; Value2: 0.1W; SizeArea_mm2: 1.28; AEC Qualified: N; VDC_V: 75V; AEC Category: Q200; SizeAreaWB_mm2: 4.68
R65 = CMP-0015817-2: RES, 0.001, 1%, 1 W, 2512; Manufacturer: Panasonic; Power_W: 1W; TempCo: ppm/C; Value_Code: 1L000; U/M: EA; Value: 0.001; EIA_Code: E96; Res_ohm: 1m; SizeX_mm: 6.3; SizeY_mm: 3.2; SizeZ_mm: 0.71; SizeArea_mm2: 20.16; AEC Category: Q200
R67 R68 = CMP-0022731-2: RES, 1.00 M, 1%, 0.125 W, 0603; Manufacturer: Vishay/Beyschlag; Power_W: 125mW; TempCo: 50 ppm/C; Value_Code: 1M00; U/M: EA; Value: 1.00Meg; EIA_Code: E96; Res_ohm: 1M; SizeX_mm: 1.6; SizeY_mm: 0.8; SizeZ_mm: 1; Value2: 0.125W; SizeArea_mm2: 1.28; AEC Qualified: N; VDC_V: 75V; AEC Category: Q200
T1 = 58599: Transformer, TH; Manufacturer: Payton; SymbolCreator: Altium; U/M: EA
TP1 TP6 = 5001: Test Point, Miniature, Black, TH; Manufacturer: Keystone; CompType: Test Point Loop; U/M: EA
TP5 = 5000: Test Point, Miniature, Red, TH; Manufacturer: Keystone; CompType: Test Point Loop; U/M: EA
U2 = UCC25630DDB: Enhanced LLC Resonant Controller with Driver, DDB0014A (SOIC-14); Manufacturer: Texas Instruments; SymbolCreator: Altium; SizeArea_mm2: 59.4; SizeAreaWB_mm2: 95.2; SizeX_mm: 6; SizeY_mm: 9.9; SizeZ_mm: 1.75; CompType: IC; U/M: EA
U5 = TL431ACDBZR: Adjustable Precision Shunt Regulator, 34 ppm / degC, 100 mA, 0 to 70 degC, 3-pin SOT-23 (DBZ), Green (RoHS & no Sb/Br); Manufacturer: Texas Instruments; Alternate PartNumber: Equivalent; Initial Accuracy @ 25/deg C(%): 1; Iout/Iz(Max)(mA): 100; Min Iz for Regulation(uA): 600; Rating: Catalog; SubFamily: Shunt Voltage Reference; Temp Coeff(Typ)(ppm/ degree C): 34; VO Adj(Max)(V): 36; VO Adj(Min)(V): 2.495
U6 U12 = VO618A: Optocoupler, 5.3 kV, 50-600% CTR, TH; Manufacturer: Vishay-Semiconductor; CTR (Min): 50%; CTR (Max): 600%; Voltage_Isolation_Vrms: 5300V; SizeAreaWB_mm2: 71.064; SizeArea_mm2: 40.304; SizeX_mm: 8.8; SizeY_mm: 4.58; SizeZ_mm: 5
U7 U8 = UCC24612-1DBVR: UCC24612-1DBV, DBV0005A (SOT-23-5); Alternate PartNumber: UCC24612-1DBVT; Manufacturer: Texas Instruments; SymbolCreator: Altium; SizeArea_mm2: 8.12; SizeAreaWB_mm2: 14.82; SizeX_mm: 2.8; SizeY_mm: 2.9; SizeZ_mm: 1.45; CompType: IC; U/M: EA
U9 = CMP-0013234-2: Bidirectional, Low- and High-Side Measurement, Multichannel, Voltage Output, Current-Sense Amplifier, DBV0006A (SOT-6); Manufacturer: Texas Instruments; SizeX_mm: 2.8; SizeY_mm: 2.9; CompType: IC; SizeZ_mm: 1.45; SizeArea_mm2: 8.12; SizeAreaWB_mm2: 14.82; U/M: EA
U10 = CMP-0074738-2: 3 Pin 100mA Fixed 5V Positive Voltage Regulator, PK0003A (SOT-3); Manufacturer: Texas Instruments; SizeZ_mm: 1.6; SizeX_mm: 4.1; SizeY_mm: 4.5; SizeArea_mm2: 18.45; CompType: IC; U/M: EA; SizeAreaWB_mm2: 28.05
U11 = CMP-0065409-1: SINGLE DIFFERENTIAL COMPARATOR, DBV0005A (SOT-23-5); Alternate PartNumber: TL331IDBVT; Alternate Manufacturer: Texas Instruments; Green_Lifecycle: Active; SizeAreaWB_mm2: 14.82; Green_REACh: Passed; U/M: EA; SizeZ_mm: 1.45; SizeX_mm: 2.8; SizeY_mm: 2.9; SizeArea_mm2: 8.12; CompType: IC

## Sheet TIDA-01495_Hardware.SchDoc: Hardware
size 431 x 279 mm; Date: Not shown in title block; ApprovedBy: Not shown in title block; CheckedBy: Not shown in title block; Author: Not shown in title block; CompanyName: Not shown in title block; DrawnBy: Ramkumar S; Engineer: Ramkumar S; Organization: Not shown in title block; Address1: Not shown in title block; Address2: Not shown in title block; Address3: Not shown in title block; Address4: Not shown in title block; DocumentNumber: 1; Revision: Use project parameter SCH_Rev; SheetNumber: 4; SheetTotal: 4; PageSetup: Record=PageOptions¦CenterHorizontal=True¦CenterVertical=True¦PrintScale=1.00¦XCorrection=1.00¦YCorrection=1.00¦PrintKind=0¦BorderSize=5000000¦LeftOffset=0¦BottomOffset=0¦Orientation=2¦PaperLength=1000¦PaperWidth=1000¦Scale=100¦PaperSource=15¦PrintQuality=600¦MediaType=1¦DitherType=10¦PaperKind=Letter¦PrintScaleMode=1
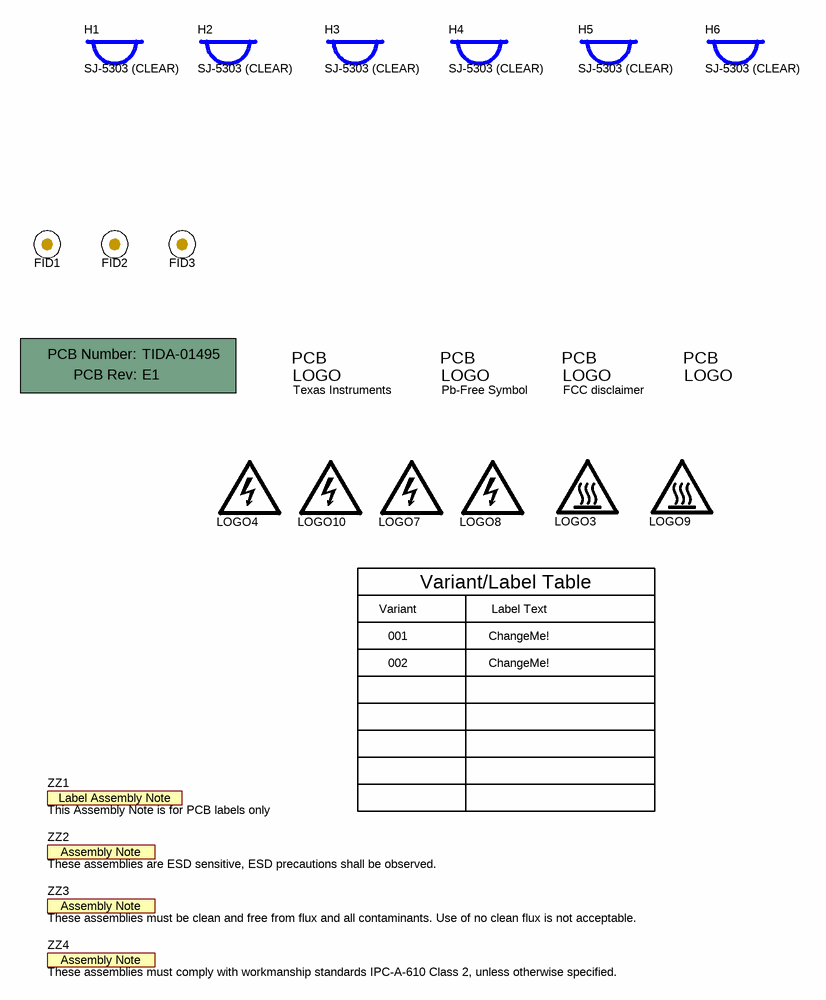
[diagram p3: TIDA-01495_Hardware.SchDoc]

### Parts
!PCB1  Printed Circuit Board  (value not drawn)  (mechanical)
FID1  Fiducial  [Fiducial10-20]  (value not drawn)
FID2  Fiducial  [Fiducial10-20]  (value not drawn)
FID3  Fiducial  [Fiducial10-20]  (value not drawn)
H1  SJ-5303 (CLEAR)  [Bumpon_SJ5003Transparent]
H2  SJ-5303 (CLEAR)  [Bumpon_SJ5003Transparent]
H3  SJ-5303 (CLEAR)  [Bumpon_SJ5003Transparent]
H4  SJ-5303 (CLEAR)  [Bumpon_SJ5003Transparent]
H5  SJ-5303 (CLEAR)  [Bumpon_SJ5003Transparent]
H6  SJ-5303 (CLEAR)  [Bumpon_SJ5003Transparent]
Logo1  Pb-Free Symbol  [Pb-Free_Overlay_Small]  (no BOM)
Logo2  ESD Susceptible  [ESD_Overlay_Small]  (value not drawn)  (no BOM)
LOGO3  CAUTION HOT SURFACE  [IEC_HotSurface_Small]  (value not drawn)  (no BOM)
LOGO4  DANGER HIGH VOLTAGE  [IEC_HighVoltage_Small]  (value not drawn)  (no BOM)
Logo5  Texas Instruments  [TI_Stacked_Overlay_Small]  (no BOM)
Logo6  FCC disclaimer  [FCC_disclaimer]  (no BOM)
LOGO7  DANGER HIGH VOLTAGE  [IEC_HighVoltage_Small]  (value not drawn)  (no BOM)
LOGO8  DANGER HIGH VOLTAGE  [IEC_HighVoltage_Small]  (value not drawn)  (no BOM)
LOGO9  CAUTION HOT SURFACE  [IEC_HotSurface_Small]  (value not drawn)  (no BOM)
LOGO10  DANGER HIGH VOLTAGE  [IEC_HighVoltage_Small]  (value not drawn)  (no BOM)
ZZ1  This Assembly Note is for PCB labels only  [AssemblyNoteLabel]  (no BOM)
ZZ2  These assemblies are ESD sensitive, ESD precautions shall be observed.  [AssemblyNote]  (no BOM)
ZZ3  These assemblies must be clean and free from flux and all contaminants. Use of no clean flux is not acceptable.  [AssemblyNote]  (no BOM)
ZZ4  These assemblies must comply with workmanship standards IPC-A-610 Class 2, unless otherwise specified.  [AssemblyNote]  (no BOM)

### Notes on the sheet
- Variant
- Variant/Label Table
- Label Text
- 001
- 002
- ChangeMe!

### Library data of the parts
!PCB1 = PCB: Manufacturer: Any; PartNumber: TIDA-01495; SymbolCreator: a0412235
FID1-FID3 = Fiducial: Fiducial mark.  There is nothing to buy or mount.; SymbolCreator: codlsc
H1-H6 = SJ-5303 (CLEAR): Bumpon, Hemisphere, 0.44 X 0.20, Clear; Manufacturer: 3M; SymbolCreator: a0412235
Logo1 = Pb-Free: SymbolCreator: a0412235
Logo2 = ESD_Susceptible: ESD Susceptible Symbol; SymbolCreator: a0412235
LOGO3 LOGO9 = IEC_HotSurface: as LOGO?#6 on sheet TIDA-01495-LLC
LOGO4 LOGO7 LOGO8 LOGO10 = IEC_HighVoltage: as LOGO?#5 on sheet TIDA-01495-LLC
Logo5 = TI_Logo: Texas Instrument Corporate Signature; SymbolCreator: codlsc
Logo6 = FCC_disclaimer: SymbolCreator: codlsc
ZZ1 = AssemblyNoteLabel: SymbolCreator: a0412235
ZZ2-ZZ4 = AssemblyNote: SymbolCreator: codlsc

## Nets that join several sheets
390V: TIDA-01495_PFC (14 pins), TIDA-01495-LLC (C2.1 Q3.2 R43.2)
AUX_15V: TIDA-01495_PFC (8 pins), TIDA-01495-LLC (D11.2)
PGND: TIDA-01495_PFC (49 pins), TIDA-01495-LLC (23 pins)
NetA: TIDA-01495_PFC (D9.1 D10.1 R11.1), TIDA-01495-LLC (R31.1)

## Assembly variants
001: not fitted FID1 FID2 FID3 R39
